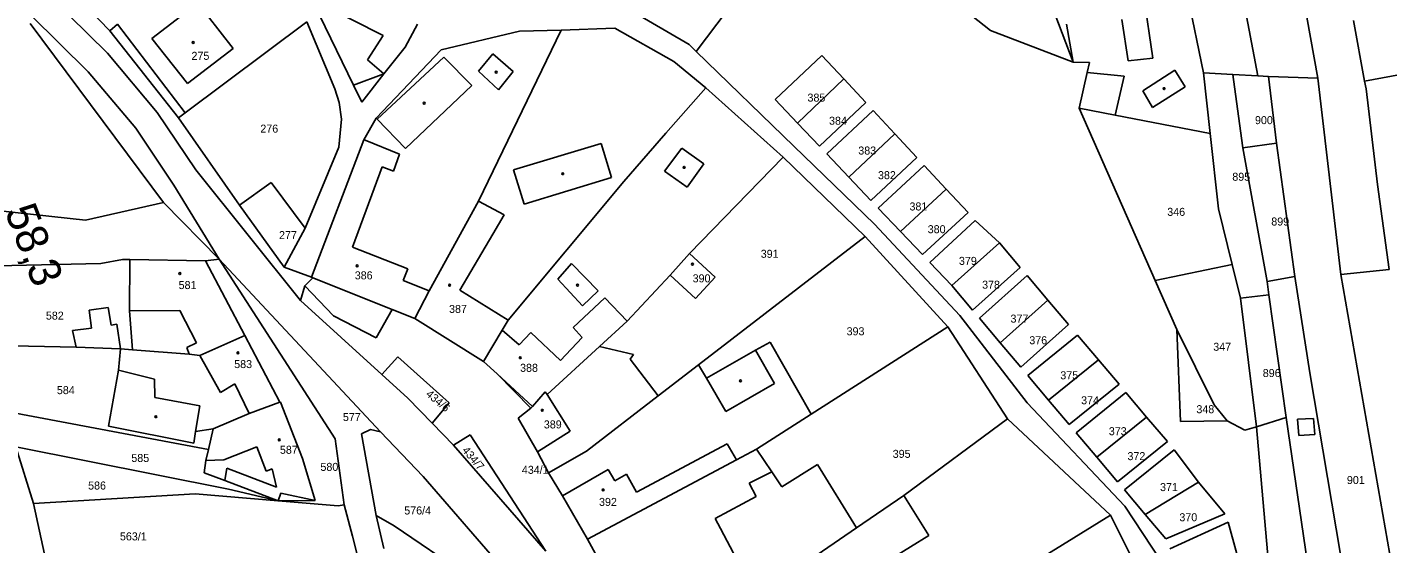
# Model space of a CAD drawing. Extents: x -563148 to -561712, y -1182311 to -1179502.
# Drawn here: x -562585.8 to -562330.8, y -1180530.4 to -1180433.7 of the extents above; entities that cross this region are included whole.
import ezdxf

# ---------------------------------------------------------------- set-up
doc = ezdxf.new("R2010")
doc.units = 0
for name, color, linetype in [('Vrstva 53', 7, 'Continuous'), ('Vrstva 55', 7, 'Continuous'), ('Vrstva 56', 7, 'Continuous'), ('Vrstva 57', 7, 'Continuous'), ('Vrstva 7', 7, 'Continuous')]:
    doc.layers.add(name, color=color, linetype=linetype)

msp = doc.modelspace()

# ---------------------------------------------------------------- linework, layer by layer
at = {"layer": 'Vrstva 53'}
for p, q in [((-562587.87, -1180512.25), (-562584.59, -1180522.85)), ((-562584.59, -1180522.85), (-562583.45, -1180528.03)), ((-562583.45, -1180528.03), (-562582.5, -1180532.33))]:
    msp.add_line(p, q, dxfattribs=at)
at = {"layer": 'Vrstva 55'}
for p, q in [((-562371.73, -1180355.72), (-562355.19, -1180442.78)), ((-562359.81, -1180354.32), (-562343.93, -1180443.2)), ((-562579.28, -1180424.9), (-562570.28, -1180434.36)), ((-562482.66, -1180424.59), (-562461.74, -1180436.9)), ((-562369.01, -1180424.42), (-562365.37, -1180442.2)), ((-562452.65, -1180427.88), (-562460.41, -1180438.19)), ((-562389.78, -1180440.23), (-562393.89, -1180429.33)), ((-562560.24, -1180466.47), (-562585.19, -1180432.97)), ((-562568.86, -1180433.08), (-562570.28, -1180434.36)), ((-562533.35, -1180432.65), (-562556.19, -1180449.71)), ((-562528.1, -1180445.2), (-562533.35, -1180432.65)), ((-562524.63, -1180444.51), (-562530.99, -1180431.39)), ((-562512.62, -1180433.06), (-562514.97, -1180437.37)), ((-562391.03, -1180433.11), (-562389.78, -1180440.23)), ((-562337.28, -1180432.4), (-562335.18, -1180443.75)), ((-562570.28, -1180434.36), (-562557.39, -1180450.6)), ((-562493.54, -1180434.41), (-562508.22, -1180437.92)), ((-562485.71, -1180434.23), (-562501.2, -1180466.24)), ((-562485.71, -1180434.23), (-562493.54, -1180434.41)), ((-562475.64, -1180433.86), (-562485.71, -1180434.23)), ((-562464.63, -1180440.08), (-562475.64, -1180433.86)), ((-562508.22, -1180437.92), (-562520.37, -1180450.67)), ((-562514.97, -1180437.37), (-562518.91, -1180442.4)), ((-562461.74, -1180436.9), (-562460.41, -1180438.19)), ((-562460.41, -1180438.19), (-562442.11, -1180455.93)), ((-562458.62, -1180445), (-562464.63, -1180440.08)), ((-562445.61, -1180447.22), (-562436.86, -1180438.94)), ((-562436.86, -1180438.94), (-562432.75, -1180443.35)), ((-562389.78, -1180440.23), (-562386.71, -1180440.26)), ((-562386.71, -1180440.26), (-562387.14, -1180442.13)), ((-562518.91, -1180442.4), (-562523.08, -1180447.71)), ((-562387.14, -1180442.13), (-562388.68, -1180448.83)), ((-562365.37, -1180442.2), (-562364.1, -1180453.55)), ((-562359.89, -1180442.51), (-562365.37, -1180442.2)), ((-562359.89, -1180442.51), (-562359.2, -1180447.54)), ((-562355.19, -1180442.78), (-562359.89, -1180442.51)), ((-562353.19, -1180442.9), (-562355.19, -1180442.78)), ((-562353.19, -1180442.9), (-562351.71, -1180455.37)), ((-562343.93, -1180443.2), (-562353.19, -1180442.9)), ((-562343.93, -1180443.2), (-562339.65, -1180479.98)), ((-562335.18, -1180443.75), (-562326.76, -1180442.19)), ((-562527.33, -1180447.77), (-562528.1, -1180445.2)), ((-562523.08, -1180447.71), (-562524.63, -1180444.51)), ((-562458.62, -1180445), (-562466.11, -1180453.47)), ((-562444.14, -1180458.01), (-562458.62, -1180445)), ((-562441.44, -1180451.61), (-562432.75, -1180443.35)), ((-562432.75, -1180443.35), (-562428.65, -1180447.77)), ((-562335.18, -1180443.75), (-562334.91, -1180445.22)), ((-562334.91, -1180445.22), (-562332.75, -1180463.14)), ((-562526.88, -1180450.87), (-562527.33, -1180447.77)), ((-562441.44, -1180451.61), (-562445.61, -1180447.22)), ((-562428.65, -1180447.77), (-562437.31, -1180455.95)), ((-562359.2, -1180447.54), (-562357.98, -1180456.26)), ((-562556.19, -1180449.71), (-562557.39, -1180450.6)), ((-562557.39, -1180450.6), (-562545.97, -1180466.97)), ((-562527.37, -1180456.15), (-562526.88, -1180450.87)), ((-562520.37, -1180450.67), (-562522.7, -1180454.74)), ((-562435.95, -1180457.38), (-562427.28, -1180449.24)), ((-562427.28, -1180449.24), (-562423.17, -1180453.65)), ((-562381.9, -1180450.13), (-562388.68, -1180448.83)), ((-562388.68, -1180448.83), (-562374.42, -1180481.11)), ((-562364.1, -1180453.55), (-562381.9, -1180450.13)), ((-562466.11, -1180453.47), (-562473.96, -1180462.57)), ((-562437.31, -1180455.95), (-562441.44, -1180451.61)), ((-562522.7, -1180454.74), (-562532.52, -1180480.45)), ((-562442.11, -1180455.93), (-562427.03, -1180470.53)), ((-562431.81, -1180461.73), (-562423.17, -1180453.65)), ((-562423.17, -1180453.65), (-562419.07, -1180458.07)), ((-562364.1, -1180453.55), (-562362.54, -1180467.66)), ((-562357.98, -1180456.26), (-562351.71, -1180455.37)), ((-562351.71, -1180455.37), (-562348.24, -1180480.35)), ((-562533.68, -1180471.27), (-562527.37, -1180456.15)), ((-562444.14, -1180458.01), (-562461.68, -1180476.02)), ((-562428.74, -1180472.82), (-562444.14, -1180458.01)), ((-562431.81, -1180461.73), (-562435.95, -1180457.38)), ((-562419.07, -1180458.07), (-562427.67, -1180466.08)), ((-562357.98, -1180456.26), (-562353.44, -1180481.3)), ((-562426.3, -1180467.53), (-562417.7, -1180459.54)), ((-562417.7, -1180459.54), (-562413.59, -1180463.96)), ((-562540.07, -1180462.72), (-562545.97, -1180466.97)), ((-562533.68, -1180471.27), (-562540.07, -1180462.72)), ((-562473.96, -1180462.57), (-562495.64, -1180488.53)), ((-562427.67, -1180466.08), (-562431.81, -1180461.73)), ((-562332.75, -1180463.14), (-562330.56, -1180479.03)), ((-562501.2, -1180466.24), (-562510.44, -1180482.99)), ((-562422.16, -1180471.89), (-562413.59, -1180463.96)), ((-562413.59, -1180463.96), (-562409.48, -1180468.37)), ((-562574.83, -1180469.79), (-562605.84, -1180466.36)), ((-562560.24, -1180466.47), (-562574.83, -1180469.79)), ((-562549.78, -1180477.08), (-562560.24, -1180466.47)), ((-562545.97, -1180466.97), (-562537.62, -1180478.58)), ((-562422.16, -1180471.89), (-562426.3, -1180467.53)), ((-562409.48, -1180468.37), (-562418.02, -1180476.24)), ((-562362.54, -1180467.66), (-562359.96, -1180478.11)), ((-562537.62, -1180478.58), (-562533.68, -1180471.27)), ((-562427.03, -1180470.53), (-562411.04, -1180487.62)), ((-562416.64, -1180477.69), (-562408.12, -1180469.84)), ((-562408.12, -1180469.84), (-562403.56, -1180474.02)), ((-562428.74, -1180472.82), (-562459.96, -1180496.85)), ((-562413.26, -1180489.74), (-562428.74, -1180472.82)), ((-562418.02, -1180476.24), (-562422.16, -1180471.89)), ((-562461.68, -1180476.02), (-562465.3, -1180480.07)), ((-562461.68, -1180476.02), (-562456.88, -1180480.46)), ((-562412.5, -1180482.04), (-562403.56, -1180474.02)), ((-562403.56, -1180474.02), (-562399.68, -1180478.62)), ((-562571.96, -1180477.88), (-562600.34, -1180478.59)), ((-562567.92, -1180477.13), (-562571.96, -1180477.88)), ((-562566.51, -1180477.17), (-562567.92, -1180477.13)), ((-562566.58, -1180486.79), (-562566.51, -1180477.17)), ((-562552.35, -1180477.39), (-562566.51, -1180477.17)), ((-562549.78, -1180477.08), (-562552.35, -1180477.39)), ((-562544.96, -1180491.41), (-562552.35, -1180477.39)), ((-562519.58, -1180509.41), (-562549.78, -1180477.08)), ((-562528.07, -1180510.71), (-562549.78, -1180477.08)), ((-562537.62, -1180478.58), (-562532.52, -1180480.45)), ((-562412.5, -1180482.04), (-562416.64, -1180477.69)), ((-562399.68, -1180478.62), (-562408.62, -1180486.63)), ((-562359.96, -1180478.11), (-562374.42, -1180481.11)), ((-562359.96, -1180478.11), (-562358.4, -1180484.42)), ((-562532.24, -1180480.56), (-562533.74, -1180482.08)), ((-562532.52, -1180480.45), (-562532.24, -1180480.56)), ((-562517.4, -1180486.53), (-562532.24, -1180480.56)), ((-562465.3, -1180480.07), (-562473.33, -1180488.72)), ((-562460.55, -1180484.44), (-562465.3, -1180480.07)), ((-562456.88, -1180480.46), (-562460.55, -1180484.44)), ((-562407.32, -1180488.16), (-562398.39, -1180480.15)), ((-562398.39, -1180480.15), (-562394.51, -1180484.74)), ((-562374.42, -1180481.11), (-562370.38, -1180490.25)), ((-562353.44, -1180481.3), (-562348.24, -1180480.35)), ((-562353.44, -1180481.3), (-562353.09, -1180483.78)), ((-562348.24, -1180480.35), (-562345.46, -1180498.35)), ((-562339.65, -1180479.98), (-562330.56, -1180479.03)), ((-562339.65, -1180479.98), (-562330.02, -1180534.86)), ((-562533.74, -1180482.08), (-562534.58, -1180484.83)), ((-562510.44, -1180482.99), (-562513.12, -1180488.2)), ((-562408.62, -1180486.63), (-562412.5, -1180482.04)), ((-562353.09, -1180483.78), (-562358.4, -1180484.42)), ((-562353.09, -1180483.78), (-562349.87, -1180506.75)), ((-562534.58, -1180484.83), (-562519.34, -1180498.67)), ((-562513.12, -1180488.2), (-562517.4, -1180486.53)), ((-562403.44, -1180492.75), (-562394.51, -1180484.74)), ((-562394.51, -1180484.74), (-562390.63, -1180489.34)), ((-562358.4, -1180484.42), (-562355.42, -1180508.51)), ((-562566.01, -1180494.04), (-562566.58, -1180486.79)), ((-562500.29, -1180496.23), (-562513.12, -1180488.2)), ((-562495.64, -1180488.53), (-562496.79, -1180490.41)), ((-562473.33, -1180488.72), (-562478.5, -1180493.44)), ((-562411.04, -1180487.62), (-562398.41, -1180504.01)), ((-562403.44, -1180492.75), (-562407.32, -1180488.16)), ((-562544.96, -1180491.41), (-562553.39, -1180495.15)), ((-562538.45, -1180503.87), (-562544.96, -1180491.41)), ((-562496.79, -1180490.41), (-562500.29, -1180496.23)), ((-562413.26, -1180489.74), (-562438.85, -1180506.08)), ((-562402.08, -1180506.97), (-562413.26, -1180489.74)), ((-562390.63, -1180489.34), (-562399.56, -1180497.34)), ((-562398.27, -1180498.87), (-562388.94, -1180491.33)), ((-562388.94, -1180491.33), (-562385.06, -1180495.92)), ((-562370.38, -1180490.25), (-562363.39, -1180504.38)), ((-562369.67, -1180507.49), (-562370.38, -1180490.25)), ((-562576.59, -1180493.55), (-562594.18, -1180493.2)), ((-562568.3, -1180493.86), (-562576.59, -1180493.55)), ((-562568.64, -1180497.85), (-562568.3, -1180493.86)), ((-562566.01, -1180494.04), (-562568.3, -1180493.86)), ((-562555.42, -1180494.87), (-562566.01, -1180494.04)), ((-562478.5, -1180493.44), (-562488.36, -1180502.43)), ((-562478.5, -1180493.44), (-562472.15, -1180494.93)), ((-562458.5, -1180499.36), (-562449.27, -1180494.13)), ((-562449.27, -1180494.13), (-562446.57, -1180492.6)), ((-562446.57, -1180492.6), (-562438.85, -1180506.08)), ((-562399.56, -1180497.34), (-562403.44, -1180492.75)), ((-562553.39, -1180495.15), (-562555.42, -1180494.87)), ((-562516.31, -1180495.35), (-562519.34, -1180498.67)), ((-562516.31, -1180495.35), (-562506.7, -1180503.99)), ((-562497.73, -1180498.58), (-562500.29, -1180496.23)), ((-562472.15, -1180494.93), (-562472.8, -1180495.84)), ((-562472.8, -1180495.84), (-562467.51, -1180502.67)), ((-562394.39, -1180503.46), (-562385.06, -1180495.92)), ((-562385.06, -1180495.92), (-562381.18, -1180500.52)), ((-562570.55, -1180508.36), (-562568.64, -1180497.85)), ((-562519.34, -1180498.67), (-562514.43, -1180503.14)), ((-562491.42, -1180504.98), (-562497.73, -1180498.58)), ((-562459.96, -1180496.85), (-562467.51, -1180502.67)), ((-562459.96, -1180496.85), (-562458.5, -1180499.36)), ((-562394.39, -1180503.46), (-562398.27, -1180498.87)), ((-562345.46, -1180498.35), (-562339.66, -1180532.39)), ((-562488.71, -1180501.92), (-562491.07, -1180504.7)), ((-562488.36, -1180502.43), (-562488.71, -1180501.92)), ((-562381.18, -1180500.52), (-562390.51, -1180508.05)), ((-562538.45, -1180503.87), (-562544.18, -1180506.01)), ((-562538.31, -1180503.85), (-562538.45, -1180503.87)), ((-562534.17, -1180514.41), (-562538.31, -1180503.85)), ((-562514.43, -1180503.14), (-562509.9, -1180507.77)), ((-562506.7, -1180503.99), (-562509.9, -1180507.77)), ((-562467.51, -1180502.67), (-562480.98, -1180513.04)), ((-562398.41, -1180504.01), (-562380.07, -1180523.31)), ((-562390.51, -1180508.05), (-562394.39, -1180503.46)), ((-562389.21, -1180509.58), (-562379.89, -1180502.05)), ((-562379.89, -1180502.05), (-562376.01, -1180506.64)), ((-562363.39, -1180504.38), (-562360.94, -1180507.38)), ((-562551.82, -1180512.73), (-562589.94, -1180505.56)), ((-562544.18, -1180506.01), (-562550.92, -1180508.83)), ((-562493.76, -1180506.86), (-562491.42, -1180504.98)), ((-562490.15, -1180513.16), (-562493.76, -1180506.86)), ((-562491.07, -1180504.7), (-562491.42, -1180504.98)), ((-562438.85, -1180506.08), (-562449.13, -1180512.64)), ((-562402.08, -1180506.97), (-562421.52, -1180521.33)), ((-562382.79, -1180524.99), (-562402.08, -1180506.97)), ((-562385.33, -1180514.17), (-562376.01, -1180506.64)), ((-562376.01, -1180506.64), (-562372.12, -1180511.24)), ((-562349.87, -1180506.75), (-562355.42, -1180508.51)), ((-562349.87, -1180506.75), (-562339.23, -1180578.72)), ((-562554.55, -1180511.52), (-562570.55, -1180508.36)), ((-562554.2, -1180509.36), (-562554.55, -1180511.52)), ((-562550.92, -1180508.83), (-562554.2, -1180509.36)), ((-562550.92, -1180508.83), (-562551.82, -1180512.73)), ((-562523.15, -1180509.82), (-562521.46, -1180508.95)), ((-562521.46, -1180508.95), (-562519.58, -1180509.41)), ((-562511.55, -1180517.78), (-562519.58, -1180509.41)), ((-562509.9, -1180507.77), (-562505.87, -1180511.9)), ((-562385.33, -1180514.17), (-562389.21, -1180509.58)), ((-562360.94, -1180507.38), (-562369.67, -1180507.49)), ((-562360.94, -1180507.38), (-562357.62, -1180509.11)), ((-562355.42, -1180508.51), (-562357.62, -1180509.11)), ((-562355.42, -1180508.51), (-562352.84, -1180537.76)), ((-562526.36, -1180523.1), (-562528.07, -1180510.71)), ((-562520.38, -1180525.07), (-562523.15, -1180509.82)), ((-562505.87, -1180511.9), (-562502.78, -1180510)), ((-562505.87, -1180511.9), (-562488.57, -1180531.74)), ((-562502.78, -1180510), (-562488.57, -1180531.74)), ((-562372.12, -1180511.24), (-562381.45, -1180518.76)), ((-562548.04, -1180520.17), (-562587.87, -1180512.25)), ((-562551.82, -1180512.73), (-562552.29, -1180514.8)), ((-562531.79, -1180522.27), (-562534.17, -1180514.41)), ((-562488.06, -1180517.1), (-562490.15, -1180513.16)), ((-562480.98, -1180513.04), (-562488.06, -1180517.1)), ((-562452.85, -1180514.65), (-562480.79, -1180529.54)), ((-562449.13, -1180512.64), (-562452.85, -1180514.65)), ((-562449.13, -1180512.64), (-562446.24, -1180516.93)), ((-562381.45, -1180518.76), (-562385.33, -1180514.17)), ((-562380.16, -1180520.29), (-562370.83, -1180512.77)), ((-562370.83, -1180512.77), (-562366.27, -1180518.86)), ((-562552.29, -1180514.8), (-562552.63, -1180517.09)), ((-562552.63, -1180517.09), (-562548.76, -1180518.56)), ((-562485.47, -1180521.41), (-562488.06, -1180517.1)), ((-562446.24, -1180516.93), (-562444.37, -1180519.71)), ((-562444.37, -1180519.71), (-562437.66, -1180515.51)), ((-562437.66, -1180515.51), (-562430.35, -1180527.42)), ((-562548.76, -1180518.56), (-562538.71, -1180522.34)), ((-562495.77, -1180535.99), (-562511.55, -1180517.78)), ((-562376.28, -1180524.88), (-562366.27, -1180518.86)), ((-562366.27, -1180518.86), (-562361.35, -1180524.75)), ((-562584.59, -1180522.85), (-562554.27, -1180521.04)), ((-562554.27, -1180521.04), (-562538.71, -1180522.34)), ((-562538.71, -1180522.34), (-562548.04, -1180520.17)), ((-562538.71, -1180522.34), (-562531.79, -1180522.27)), ((-562480.79, -1180529.54), (-562485.47, -1180521.41)), ((-562421.52, -1180521.33), (-562430.35, -1180527.42)), ((-562376.28, -1180524.88), (-562380.16, -1180520.29)), ((-562538.71, -1180522.34), (-562527.49, -1180523.28)), ((-562527.49, -1180523.28), (-562526.36, -1180523.1)), ((-562380.07, -1180523.31), (-562366.65, -1180543.76)), ((-562372.39, -1180529.47), (-562376.28, -1180524.88)), ((-562361.35, -1180524.75), (-562372.39, -1180529.47)), ((-562520.38, -1180525.07), (-562517.01, -1180527.03)), ((-562517.01, -1180527.03), (-562499.87, -1180538.59)), ((-562430.35, -1180527.42), (-562445.81, -1180537.93)), ((-562382.79, -1180524.99), (-562412.44, -1180543.32)), ((-562382.79, -1180524.99), (-562369.45, -1180551.74)), ((-562360.73, -1180526.3), (-562371.65, -1180531.32)), ((-562359.12, -1180532.26), (-562360.73, -1180526.3)), ((-562478.88, -1180532.92), (-562480.79, -1180529.54))]:
    msp.add_line(p, q, dxfattribs=at)
at = {"layer": 'Vrstva 56'}
for p, q in [((-562377.32, -1180422.51), (-562374.84, -1180439.44)), ((-562581.94, -1180427.49), (-562570.69, -1180438.52)), ((-562405.25, -1180434.26), (-562414.16, -1180427.24)), ((-562562.4, -1180435.8), (-562553.54, -1180429)), ((-562519.09, -1180435.24), (-562530.82, -1180429.27)), ((-562574.36, -1180442), (-562585.08, -1180431.4)), ((-562556.19, -1180449.71), (-562568.86, -1180433.08)), ((-562552.04, -1180431.38), (-562547.17, -1180437.63)), ((-562379.45, -1180439.95), (-562380.63, -1180432.22)), ((-562522.01, -1180439.79), (-562519.09, -1180435.24)), ((-562389.78, -1180440.23), (-562405.25, -1180434.26)), ((-562555.74, -1180444.21), (-562562.4, -1180435.8)), ((-562547.17, -1180437.63), (-562555.74, -1180444.21)), ((-562570.69, -1180438.52), (-562561.41, -1180449.62)), ((-562518.91, -1180442.4), (-562522.01, -1180439.79)), ((-562520.16, -1180450.89), (-562507.69, -1180439.28)), ((-562507.69, -1180439.28), (-562502.43, -1180444.55)), ((-562501.22, -1180441.86), (-562498.52, -1180438.62)), ((-562498.52, -1180438.62), (-562494.69, -1180441.96)), ((-562374.84, -1180439.44), (-562379.45, -1180439.95)), ((-562574.36, -1180442), (-562565.43, -1180452.57)), ((-562518.91, -1180442.4), (-562524.63, -1180444.51)), ((-562497.46, -1180445.39), (-562501.22, -1180441.86)), ((-562494.69, -1180441.96), (-562497.46, -1180445.39)), ((-562387.14, -1180442.13), (-562380.22, -1180442.81)), ((-562380.22, -1180442.81), (-562381.9, -1180450.13)), ((-562376.71, -1180445.56), (-562370.75, -1180441.71)), ((-562370.75, -1180441.71), (-562368.79, -1180444.83)), ((-562502.43, -1180444.55), (-562514.85, -1180456.39)), ((-562374.89, -1180448.68), (-562376.71, -1180445.56)), ((-562368.79, -1180444.83), (-562374.89, -1180448.68)), ((-562561.41, -1180449.62), (-562554.18, -1180460.39)), ((-562514.85, -1180456.39), (-562520.16, -1180450.89)), ((-562565.43, -1180452.57), (-562558.29, -1180463.24)), ((-562522.7, -1180454.74), (-562522.44, -1180454.84)), ((-562522.44, -1180454.84), (-562516.02, -1180457.46)), ((-562494.62, -1180460.35), (-562478.22, -1180455.43)), ((-562478.22, -1180455.43), (-562476.27, -1180461.8)), ((-562516.02, -1180457.46), (-562517.11, -1180460.62)), ((-562466.34, -1180460.62), (-562463.13, -1180456.32)), ((-562463.13, -1180456.32), (-562459.01, -1180459.25)), ((-562534.58, -1180484.83), (-562554.18, -1180460.39)), ((-562519.28, -1180459.79), (-562524.8, -1180474.83)), ((-562517.11, -1180460.62), (-562519.28, -1180459.79)), ((-562492.65, -1180466.8), (-562494.62, -1180460.35)), ((-562462.09, -1180463.58), (-562466.34, -1180460.62)), ((-562459.01, -1180459.25), (-562462.09, -1180463.58)), ((-562558.29, -1180463.24), (-562549.78, -1180477.08)), ((-562476.27, -1180461.8), (-562492.65, -1180466.8)), ((-562501.2, -1180466.24), (-562496.39, -1180468.79)), ((-562496.39, -1180468.79), (-562498.54, -1180472.43)), ((-562498.54, -1180472.43), (-562504.72, -1180482.87)), ((-562524.8, -1180474.83), (-562514.46, -1180478.9)), ((-562514.46, -1180478.9), (-562515.33, -1180481.07)), ((-562486.36, -1180480.81), (-562483.78, -1180477.92)), ((-562483.78, -1180477.92), (-562478.78, -1180483.01)), ((-562515.33, -1180481.07), (-562510.44, -1180482.99)), ((-562481.7, -1180485.81), (-562486.36, -1180480.81)), ((-562528.37, -1180487.71), (-562533.74, -1180482.08)), ((-562504.72, -1180482.87), (-562495.64, -1180488.53)), ((-562478.78, -1180483.01), (-562481.7, -1180485.81)), ((-562574.14, -1180486.63), (-562570.62, -1180486.15)), ((-562573.7, -1180489.99), (-562574.14, -1180486.63)), ((-562570.62, -1180486.15), (-562570.03, -1180489.45)), ((-562517.4, -1180486.53), (-562520.38, -1180491.8)), ((-562483.48, -1180489.91), (-562477.53, -1180484.31)), ((-562477.53, -1180484.31), (-562473.33, -1180488.72)), ((-562557.14, -1180486.67), (-562566.58, -1180486.79)), ((-562554.05, -1180492.74), (-562557.14, -1180486.67)), ((-562520.38, -1180491.8), (-562528.37, -1180487.71)), ((-562577.27, -1180490.46), (-562573.7, -1180489.99)), ((-562576.59, -1180493.55), (-562577.27, -1180490.46)), ((-562570.03, -1180489.45), (-562568.95, -1180489.26)), ((-562568.95, -1180489.26), (-562568.3, -1180493.86)), ((-562496.79, -1180490.41), (-562493.58, -1180493.12)), ((-562493.58, -1180493.12), (-562491.38, -1180490.79)), ((-562491.38, -1180490.79), (-562485.85, -1180496.08)), ((-562485.85, -1180496.08), (-562481.8, -1180491.74)), ((-562481.8, -1180491.74), (-562483.48, -1180489.91)), ((-562555.86, -1180493.65), (-562554.05, -1180492.74)), ((-562555.42, -1180494.87), (-562555.86, -1180493.65)), ((-562449.27, -1180494.13), (-562445.71, -1180500.39)), ((-562549.55, -1180502.04), (-562553.39, -1180495.15)), ((-562568.64, -1180497.85), (-562561.88, -1180499.54)), ((-562491.07, -1180504.7), (-562497.73, -1180498.58)), ((-562454.85, -1180505.59), (-562458.5, -1180499.36)), ((-562561.88, -1180499.54), (-562561.85, -1180503.02)), ((-562546.88, -1180500.46), (-562549.55, -1180502.04)), ((-562544.18, -1180506.01), (-562546.88, -1180500.46)), ((-562445.71, -1180500.39), (-562454.85, -1180505.59)), ((-562561.85, -1180503.02), (-562553.41, -1180504.52)), ((-562488.36, -1180502.43), (-562484.03, -1180509.32)), ((-562553.41, -1180504.52), (-562554.2, -1180509.36)), ((-562347.75, -1180507.05), (-562344.73, -1180506.89)), ((-562344.73, -1180506.89), (-562344.47, -1180509.93)), ((-562484.03, -1180509.32), (-562490.15, -1180513.16)), ((-562347.51, -1180510.12), (-562347.75, -1180507.05)), ((-562471.61, -1180520.7), (-562454.6, -1180511.65)), ((-562454.6, -1180511.65), (-562452.85, -1180514.65)), ((-562344.47, -1180509.93), (-562347.51, -1180510.12)), ((-562548.93, -1180514.66), (-562552.29, -1180514.8)), ((-562542.72, -1180512.24), (-562548.93, -1180514.66)), ((-562540.96, -1180516.77), (-562542.72, -1180512.24)), ((-562548.76, -1180518.56), (-562548.34, -1180516.21)), ((-562548.34, -1180516.21), (-562539.03, -1180519.79)), ((-562539.87, -1180516.37), (-562540.96, -1180516.77)), ((-562539.03, -1180519.79), (-562539.87, -1180516.37)), ((-562485.47, -1180521.41), (-562476.92, -1180516.48)), ((-562476.92, -1180516.48), (-562475.64, -1180518.61)), ((-562446.24, -1180516.93), (-562450.47, -1180519.05)), ((-562475.64, -1180518.61), (-562473.47, -1180517.35)), ((-562473.47, -1180517.35), (-562471.61, -1180520.7)), ((-562450.47, -1180519.05), (-562449.16, -1180521.51)), ((-562538.71, -1180522.34), (-562538.25, -1180520.92)), ((-562538.25, -1180520.92), (-562531.79, -1180522.27)), ((-562449.16, -1180521.51), (-562456.84, -1180525.66)), ((-562421.52, -1180521.33), (-562416.85, -1180528.81)), ((-562526.36, -1180523.1), (-562524.83, -1180528.98)), ((-562520.38, -1180525.07), (-562518.95, -1180531.25)), ((-562456.84, -1180525.66), (-562455.87, -1180527.5)), ((-562524.83, -1180528.98), (-562523.61, -1180533.63)), ((-562455.87, -1180527.5), (-562452.77, -1180533.35)), ((-562416.85, -1180528.81), (-562423.69, -1180533.09))]:
    msp.add_line(p, q, dxfattribs=at)
at = {"layer": 'Vrstva 57'}
for centre in [(-562554.65, -1180436.52), (-562497.89, -1180442.07), (-562372.75, -1180445.16), (-562511.37, -1180447.89), (-562485.43, -1180461.09), (-562462.67, -1180459.9), (-562523.95, -1180478.35), (-562461.12, -1180478.01), (-562557.15, -1180479.79), (-562506.61, -1180481.96), (-562482.64, -1180481.94), (-562546.27, -1180494.64), (-562493.37, -1180495.54), (-562452.11, -1180499.88), (-562561.65, -1180506.58), (-562489.25, -1180505.38), (-562538.53, -1180510.92), (-562477.86, -1180520.3)]:
    msp.add_circle(centre, 0.175, dxfattribs=at)

# ---------------------------------------------------------------- texts
for s, p in [('275', (-562554.98, -1180439.77)), ('385', (-562439.56, -1180447.59)), ('384', (-562435.52, -1180451.92)), ('900', (-562355.71, -1180451.81)), ('276', (-562542.08, -1180453.4)), ('383', (-562430.04, -1180457.5)), ('382', (-562426.35, -1180462.11)), ('895', (-562359.96, -1180462.41)), ('381', (-562420.45, -1180467.97)), ('346', (-562372.15, -1180468.98)), ('380', (-562417.03, -1180472.23)), ('899', (-562352.66, -1180470.79)), ('277', (-562538.58, -1180473.34)), ('391', (-562448.32, -1180476.83)), ('379', (-562411.18, -1180478.16)), ('581', (-562557.39, -1180482.69)), ('386', (-562524.39, -1180480.87)), ('390', (-562461.08, -1180481.43)), ('378', (-562406.84, -1180482.62)), ('387', (-562506.72, -1180487.16)), ('582', (-562582.26, -1180488.41)), ('377', (-562401.52, -1180488.97)), ('393', (-562432.23, -1180491.34)), ('376', (-562398, -1180493.02)), ('347', (-562363.53, -1180494.24)), ('583', (-562546.98, -1180497.48)), ('388', (-562493.41, -1180498.18)), ('375', (-562392.19, -1180499.58)), ('896', (-562354.25, -1180499.16)), ('584', (-562580.2, -1180502.36)), ('374', (-562388.29, -1180504.26)), ('348', (-562366.69, -1180505.93)), ('577', (-562526.61, -1180507.39)), ('389', (-562488.96, -1180508.78)), ('373', (-562383.1, -1180510.05)), ('587', (-562538.41, -1180513.53)), ('585', (-562566.25, -1180515.06)), ('395', (-562423.59, -1180514.29)), ('372', (-562379.61, -1180514.72)), ('580', (-562530.82, -1180516.73)), ('434/1', (-562493.08, -1180517.28)), ('586', (-562574.35, -1180520.22)), ('371', (-562373.5, -1180520.51)), ('901', (-562338.49, -1180519.19)), ('392', (-562478.62, -1180523.29)), ('576/4', (-562515.11, -1180524.89)), ('370', (-562369.88, -1180526.16))]:
    msp.add_text(s, height=1.5, dxfattribs=at).set_placement(p)
for s, rotation, p in [('434/6', 319.8029, (-562511.18, -1180502.56)), ('434/7', 310.3418, (-562504.37, -1180512.94)), ('563/1', 359.6709, (-562568.39, -1180529.73))]:
    msp.add_text(s, height=1.5, rotation=rotation, dxfattribs=at).set_placement(p)
at = {"layer": 'Vrstva 7'}
msp.add_text('58,3', height=6, rotation=290.9979, dxfattribs=at).set_placement((-562590.03, -1180468.11))

doc.saveas('drawing.dxf')
